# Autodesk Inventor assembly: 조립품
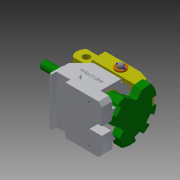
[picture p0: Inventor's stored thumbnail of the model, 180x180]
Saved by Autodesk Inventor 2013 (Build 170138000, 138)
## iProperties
Created: 2016-11
Part Number: 조립품
Document SubType Name: Assembly
Designer: Administrator
Author: Administrator
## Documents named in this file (8)
- C:\Users\Administrator\Desktop\461107V1016\조립품.iam
- C:\Users\Administrator\Desktop\461107V1016\본체.ipt
- C:\Users\Administrator\Desktop\461107V1016\부시.ipt
- C:\Users\Administrator\Desktop\461107V1016\분할대.ipt
- C:\Users\Administrator\Desktop\461107V1016\분할축.ipt
- C:\Users\Administrator\Desktop\461107V1016\와셔.ipt
- C:\Users\Administrator\Desktop\461107V1016\원통형핀.ipt
- C:\Users\Administrator\Desktop\461107V1016\클레비스핀.ipt
